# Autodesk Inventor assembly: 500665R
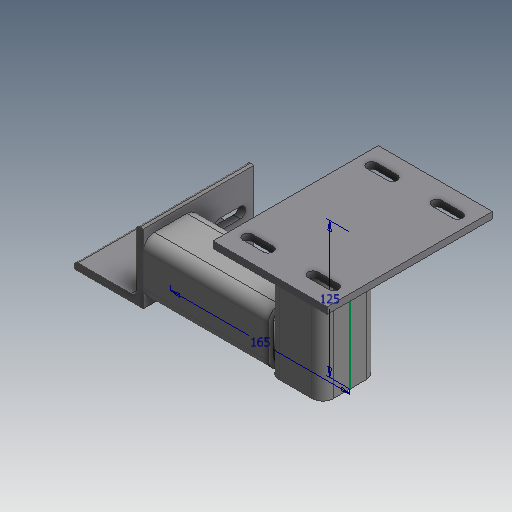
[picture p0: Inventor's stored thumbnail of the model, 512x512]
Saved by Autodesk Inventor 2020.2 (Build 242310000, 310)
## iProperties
_SolveAssemblyDoc: Frame Generator Solve Assembly
_Version: 15.0.0
Shininess: 0.0
Length Units: 11269
Angle Units: 11279
Time Units: 11290
Mass Units: 11283
Length Display Precision: 3
Angle Display Precision: 2
Compacted: True
Created: 2000-02
Part Number: 500665R
Document SubType Name: Assembly
Description: WMT-CP,TU,XX,ADJUSTABLE RAIL MOUNT,HOPPER PAN
Designer: sspink
Mass: 1547.65 g
Surface Area: 1487.37 cm^2
Volume: 372.477 cm^3
Density: 4.15501 g/cm^3
Density: 0.0
Volumn: 0.0
Area: 0.0
PropertySet Name: Model Information
Control State: 0
Checked Out: False
Master: False
Dimensions: 137x152,6x283,5 mm
Mass: 1,548 kg
DocNumber: 500665L.iam
Folder: 01 - Themengebiete\Simplification\01 - Packaging machine\
VDS_Category: 3D Komponenten
Author: sspink
Revision Number: -
Title: 500665L
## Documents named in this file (5)
- D:\07 - DEMODATEN\OTX 2019 - Dataset - UPDATE - Dez2019\Designs\07-Packing machine\500665R.iam
- D:\07 - DEMODATEN\OTX 2019 - Dataset - UPDATE - Dez2019\Designs\07-Packing machine\Parts\ADSK-011642.ipt
- D:\07 - DEMODATEN\OTX 2019 - Dataset - UPDATE - Dez2019\Designs\07-Packing machine\Parts\ADSK-014426.ipt
- D:\07 - DEMODATEN\OTX 2019 - Dataset - UPDATE - Dez2019\Designs\07-Packing machine\500665L\Frame\ADSK-014427.iam
- D:\07 - DEMODATEN\OTX 2019 - Dataset - UPDATE - Dez2019\Designs\07-Packing machine\Parts\ADSK-014436.ipt
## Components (4 placed, 4 different names)
1. ADSK-014426:1
2. ADSK-011642:1 — Passend:6, Fluchtend:7, Fluchtend:10
3. ADSK-014427:1 [sub-assembly] — Passend:6, Fluchtend:7, Fluchtend:10, Fluchtend:11, Passend:7, Fluchtend:12
4. ADSK-014436:1 — Fluchtend:11, Passend:7, Fluchtend:12
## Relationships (6: Flush 4, Mate 2)
- Passend:6 [Mate]: ADSK-011642:1 ↔ ADSK-014427:1
- Fluchtend:7 [Flush]: ADSK-011642:1 ↔ ADSK-014427:1
- Fluchtend:10 [Flush]: ADSK-011642:1 ↔ ADSK-014427:1
- Fluchtend:11 [Flush]: ADSK-014427:1 ↔ ADSK-014436:1
- Passend:7 [Mate]: ADSK-014427:1 ↔ ADSK-014436:1
- Fluchtend:12 [Flush]: ADSK-014427:1 ↔ ADSK-014436:1
